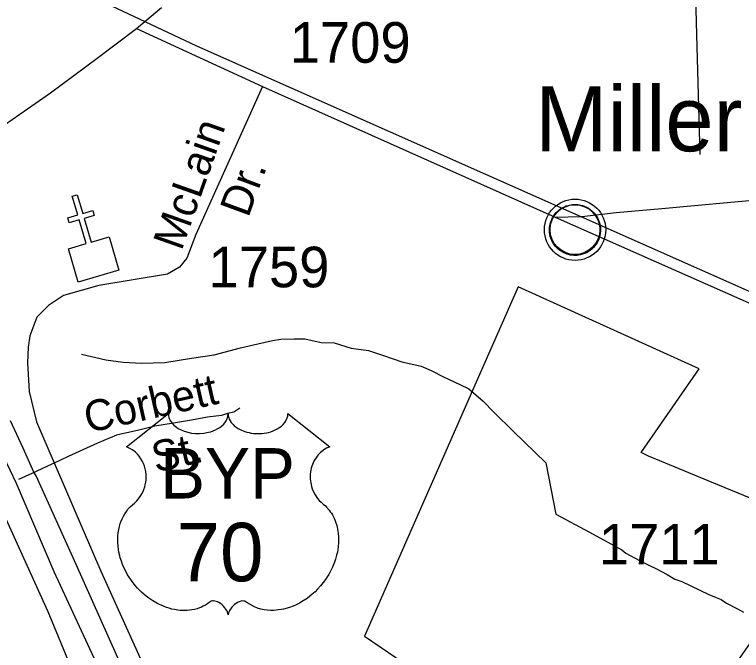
# Model space of a CAD drawing. Extents: x 2260773 to 2342389, y 552869 to 618546.
# Drawn here: x 2317310 to 2319547, y 592888 to 594846 of the extents above; entities that cross this region are included whole.
import ezdxf

# ---------------------------------------------------------------- set-up
doc = ezdxf.new("R2010")
doc.units = 0
for name, color, linetype in [('Exist Boundary Political City Limit New', 7, 'Continuous'), ('Exist Civil Demographics Community CELL', 7, 'Continuous'), ('Exist Civil Demographics Community Label', 7, 'Continuous'), ('Exist Cultural Church CELL', 7, 'Continuous'), ('Exist Hydrographic Misc Water Feature', 7, 'Continuous'), ('Exist Railroad Mainline', 7, 'Continuous'), ('Exist Road Non-System Type 51', 7, 'Continuous'), ('Exist Road Non-System Type 51 Label', 7, 'Continuous'), ('Exist Road Primary US Divided Attributed', 7, 'Continuous'), ('Exist Road Primary US Service Attributed', 7, 'Continuous'), ('Exist Road Primary US Shield CELL', 7, 'Continuous'), ('Exist Road Primary US Shield Number Label', 7, 'Continuous'), ('Exist Road Primary US UnDivided 4 Lane Attributed', 7, 'Continuous'), ('Exist Road Secondary Type 51 Attributed', 7, 'Continuous'), ('Exist Road Secondary Type 51 Label', 7, 'Continuous'), ('Exist Road Secondary Type 51 Number Label', 7, 'Continuous'), ('Map Preparation Boundary City Limit Buffer Line', 7, 'Continuous')]:
    doc.layers.add(name, color=color, linetype=linetype)

msp = doc.modelspace()

# ---------------------------------------------------------------- linework, layer by layer
at = {"layer": 'Exist Boundary Political City Limit New'}
msp.add_lwpolyline([(2319699.5, 593306.2), (2319462.5, 593403.4), (2319296, 593471.8), (2319261, 593486.1), (2319239, 593497.4), (2319416.8, 593755.6), (2318860, 594007.6), (2318730.8, 593714.1), (2318386.5, 592932.1), (2318483.8, 592866.8), (2318723.8, 592705.5), (2318740.8, 592693.9), (2318747.5, 592689.4), (2319027, 592500), (2319132.2, 592428), (2319184.8, 592392.1), (2319171.5, 592367.5), (2319166.5, 592358.4), (2319165, 592354.4), (2319162.2, 592346.7), (2319155.5, 592327.6), (2319153.8, 592322.2), (2319152.2, 592313.9)], dxfattribs=at)
at = {"layer": 'Exist Civil Demographics Community CELL'}
msp.add_lwpolyline([(2318957.4, 594195.7), (2318958.4, 594201.3), (2318960.2, 594207.9), (2318963.1, 594215.1), (2318966, 594220.8), (2318969.4, 594226.6), (2318973.1, 594231.7), (2318977.1, 594236.1), (2318981.7, 594240.7), (2318987.2, 594245.2), (2318992.6, 594248.9), (2318997.5, 594251.8), (2319002.6, 594254.2), (2319008, 594256.5), (2319013.7, 594258.3), (2319018, 594259.5), (2319022.8, 594260.2), (2319027, 594261), (2319033.3, 594261.2), (2319037.8, 594261.1), (2319043.4, 594260.8), (2319048.3, 594260.1), (2319053.2, 594259.1), (2319058.2, 594257.7), (2319063.4, 594255.8), (2319070.1, 594252.9), (2319076.3, 594249.4), (2319081.4, 594245.8), (2319086.6, 594241.8), (2319089.9, 594238.7), (2319094, 594234.3), (2319097.8, 594229.6), (2319100.9, 594225), (2319104.1, 594220), (2319106.5, 594214.8), (2319108.5, 594209.8), (2319110.1, 594204.8), (2319111.4, 594200.2), (2319112.5, 594194.2), (2319113.1, 594189.5), (2319113.4, 594183.5), (2319113.2, 594177.7), (2319112.6, 594172), (2319111.7, 594166.5), (2319110, 594160.4), (2319108.2, 594154.5), (2319105.9, 594149.4), (2319102.7, 594143.4), (2319099.4, 594138.1), (2319096, 594133.4), (2319091.7, 594128.7), (2319086.4, 594123.7), (2319081.4, 594119.6), (2319076.4, 594116.2), (2319072.1, 594113.7), (2319065.3, 594110.4), (2319058.1, 594107.7), (2319052.2, 594106.2), (2319045.6, 594104.9), (2319041.2, 594104.5), (2319036.7, 594104.2), (2319031.1, 594104.2), (2319026.8, 594104.6), (2319021.2, 594105.4), (2319015.2, 594106.7), (2319010.7, 594108), (2319005.5, 594109.8), (2319000.9, 594111.8), (2318997, 594114.1), (2318990.2, 594118.1), (2318984.6, 594122.4), (2318979.7, 594126.9), (2318975.2, 594131.8), (2318972, 594135.7), (2318969.1, 594139.9), (2318965, 594147), (2318963.3, 594150.5), (2318961.5, 594154.6), (2318958.9, 594162.8), (2318957.4, 594169.8), (2318956.7, 594175), (2318956.4, 594181.3), (2318956.3, 594186), (2318956.9, 594192.4)], close=True, dxfattribs=at)
for centre, radius in [((2319035, 594183.3), 94.3), ((2319034.8, 594183.6), 76.7)]:
    msp.add_circle(centre, radius, dxfattribs=at)
at = {"layer": 'Exist Cultural Church CELL'}
msp.add_lwpolyline([(2317475.4, 594124.4), (2317530, 594140.5), (2317508.7, 594213.6), (2317478, 594204.6), (2317473.5, 594220), (2317504.2, 594228.9), (2317487.4, 594286.7), (2317502.7, 594291.1), (2317519.6, 594233.4), (2317550.3, 594242.4), (2317554.8, 594227), (2317524.1, 594218.1), (2317545.4, 594145), (2317600.8, 594161), (2317630.6, 594058.8), (2317505.2, 594022.2)], close=True, dxfattribs=at)
at = {"layer": 'Exist Hydrographic Misc Water Feature'}
for points in [[(2319420.4, 594414.5), (2319411, 594746), (2319397.6, 595243.6), (2319386.4, 595709.2), (2319385.5, 595793.3), (2319373.8, 595807.2)], [(2317516.1, 593800.4), (2317590.3, 593783.2), (2317644.2, 593775.5), (2317700.2, 593772.3), (2317772, 593774.9), (2317854, 593787.7), (2317923.9, 593798.7), (2318005.5, 593819.7), (2318059.1, 593832.3), (2318103.3, 593842.6), (2318129.2, 593846.9), (2318170.8, 593847.5), (2318203.2, 593847.5), (2318253.2, 593836.3), (2318293.2, 593834.7), (2318345.5, 593819.1), (2318399, 593811.9), (2318445.4, 593796), (2318501.8, 593777), (2318561.8, 593763.5), (2318592, 593750), (2318630.3, 593730.1), (2318680.4, 593706.7), (2318708.2, 593693.2), (2318752.7, 593655.7), (2318785.3, 593622), (2318846, 593562.6), (2318944.7, 593465.8), (2318976.3, 593308.2), (2319079.6, 593252.8), (2319179.3, 593198.1), (2319191.8, 593188.1)], [(2319191.8, 593188.1), (2319233.6, 593164.8), (2319261.9, 593150.8), (2319285.9, 593139.1), (2319318.3, 593121.7), (2319342.3, 593107.9), (2319364, 593100.1), (2319446.8, 593060.9), (2319469, 593051.1), (2319485, 593045.4), (2319501, 593033.7), (2319535.4, 593016), (2319553.3, 593006.4)]]:
    msp.add_lwpolyline(points, dxfattribs=at)
at = {"layer": 'Exist Railroad Mainline'}
msp.add_line((2319052.5, 594224), (2320133.5, 593744), dxfattribs=at)
for points in [[(2316516.4, 595368.8), (2316557.9, 595354.7), (2316569.9, 595349.3), (2317194.7, 595067.6), (2317710.7, 594824.1)], [(2317710.7, 594824.1), (2317869.9, 594749), (2319052.5, 594224)]]:
    msp.add_lwpolyline(points, dxfattribs=at)
at = {"layer": 'Exist Road Non-System Type 51'}
for p, q in [((2317431.4, 593464.8), (2317424.1, 593461.5)), ((2317424.1, 593461.5), (2317362.6, 593433)), ((2317362.6, 593433), (2317321.8, 593414.1))]:
    msp.add_line(p, q, dxfattribs=at)
msp.add_lwpolyline([(2318003.4, 593634.5), (2317984.9, 593622.2), (2317964.9, 593617.5), (2317946.4, 593611.4), (2317903.4, 593606.8), (2317854.1, 593597.5), (2317798.8, 593588.3), (2317741.8, 593579.1), (2317692.6, 593566.8), (2317623.4, 593551.4), (2317564.9, 593526.7), (2317475.3, 593485.2), (2317431.4, 593464.8)], dxfattribs=at)
at = {"layer": 'Exist Road Primary US Divided Attributed'}
for points in [[(2318409.9, 591133.5), (2318220.5, 591549.2), (2318116.4, 591784.8), (2318091.6, 591843.1), (2318003.6, 592025.4), (2317970.1, 592106), (2317773, 592538.8), (2317499.1, 593152.7), (2317376.4, 593425.6), (2317369, 593436.7), (2317336.4, 593511.1), (2317297.8, 593595.3)], [(2317244.4, 593554), (2317265.1, 593510), (2317275.6, 593485.4), (2317314.4, 593403.3), (2317430.9, 593131.7), (2317716, 592515.3), (2317901.9, 592097.3), (2317947.8, 591995.6), (2318043.2, 591788.5), (2318070.5, 591727.7), (2318162.2, 591525.6), (2318372.4, 591066)]]:
    msp.add_lwpolyline(points, dxfattribs=at)
at = {"layer": 'Exist Road Primary US Service Attributed'}
msp.add_lwpolyline([(2316236.2, 593337.5), (2316558.7, 593496.8), (2316840.8, 593657.8), (2316918.8, 593687.9), (2316952.1, 593687.9), (2316985.3, 593677.8), (2317054.8, 593635.8), (2317111.3, 593580.8), (2317193.8, 593470.7), (2317228.5, 593407), (2317257.5, 593347.6), (2317412.3, 593007.9), (2317565.7, 592636.1), (2317936, 591832.5), (2318136.5, 591414.9), (2318181.6, 591293.3), (2318199.7, 591210.5), (2318199.7, 591136.7), (2318153.2, 590967.3), (2318163.6, 590922.3), (2318178, 590893.3), (2318207, 590860), (2318239.5, 590837.1)], dxfattribs=at)
at = {"layer": 'Exist Road Primary US Shield CELL'}
msp.add_lwpolyline([(2317783.3, 593617.3), (2317783.6, 593612), (2317784.9, 593605.7), (2317785.9, 593602.4), (2317788.9, 593596.2), (2317793.7, 593588.8), (2317800.5, 593581.6), (2317808.2, 593575.3), (2317813.4, 593571.9), (2317822.2, 593567.2), (2317832.1, 593563), (2317843.2, 593559.8), (2317854.5, 593557.6), (2317866.9, 593556.2), (2317879.1, 593556), (2317892.3, 593556.9), (2317906.9, 593559.8), (2317913.7, 593561.5), (2317921.2, 593564.1), (2317928.2, 593567), (2317935.8, 593571.1), (2317942, 593575), (2317946.8, 593578.5), (2317953.7, 593585.1), (2317959.1, 593591.8), (2317961.4, 593595.6), (2317963.3, 593599.3), (2317966, 593607), (2317966.8, 593610.4), (2317967.3, 593617.6), (2317967.8, 593611.6), (2317968.4, 593607.9), (2317969.4, 593604.2), (2317970.9, 593600.3), (2317973.6, 593594.9), (2317976.7, 593590.3), (2317982.4, 593583.5), (2317986, 593580.2), (2317989.2, 593577.5), (2317998, 593571.5), (2318008.2, 593566.4), (2318013.2, 593564.2), (2318018.4, 593562.3), (2318024.9, 593560.4), (2318031.7, 593558.8), (2318038.3, 593557.6), (2318045.2, 593556.6), (2318052.2, 593556.1), (2318057.9, 593556), (2318064.8, 593556), (2318071.3, 593556.4), (2318077.9, 593557.2), (2318085.2, 593558.4), (2318091, 593559.7), (2318098.8, 593561.7), (2318105.8, 593564.2), (2318111.9, 593566.9), (2318119.9, 593571.1), (2318126.4, 593575.1), (2318131.1, 593578.9), (2318136.7, 593584.1), (2318142, 593590.2), (2318145.1, 593594.7), (2318147.3, 593599.3), (2318149.4, 593604.2), (2318150.6, 593609.4), (2318151.2, 593613.9), (2318151.4, 593617.7), (2318280, 593515.2), (2318276.9, 593514.1), (2318269.9, 593510.7), (2318264.4, 593507.4), (2318255.5, 593501.2), (2318251.8, 593497.8), (2318248, 593494.2), (2318244.5, 593490.4), (2318241.4, 593486.8), (2318237.7, 593481.6), (2318234.3, 593476.5), (2318231.1, 593470.8), (2318228.7, 593465.8), (2318224.7, 593455.5), (2318222.8, 593449), (2318221.6, 593443.4), (2318220.1, 593431.9), (2318219.7, 593426.5), (2318219.7, 593421.1), (2318220, 593415.4), (2318220.5, 593409.9), (2318221.5, 593404.2), (2318222.4, 593399.2), (2318224, 593393), (2318226.3, 593385.9), (2318229.1, 593379), (2318235, 593367.8), (2318242.6, 593356.4), (2318247.9, 593350), (2318253.3, 593344.6), (2318261.2, 593337.9), (2318265.5, 593334.1), (2318270.4, 593329.1), (2318278.5, 593319.8), (2318281.7, 593315.4), (2318285, 593310.4), (2318288.1, 593305.4), (2318291.1, 593299.9), (2318293.6, 593295.1), (2318298.1, 593284.1), (2318301.4, 593273.4), (2318302.9, 593267.7), (2318305.3, 593255.1), (2318306.2, 593248.9), (2318307.2, 593236.6), (2318307.2, 593221.7), (2318306.1, 593207.6), (2318303.4, 593191.1), (2318301.2, 593181.2), (2318297.8, 593169.7), (2318294.6, 593159.8), (2318288.7, 593145.1), (2318283.5, 593134.5), (2318276.7, 593122), (2318272.1, 593114.5), (2318266.7, 593106.4), (2318260, 593097.2), (2318252, 593087.3), (2318242.6, 593076.9), (2318234.9, 593069.2), (2318224.9, 593060.2), (2318218.8, 593055.2), (2318210.1, 593048.7), (2318198.3, 593040.8), (2318186.6, 593034), (2318176.6, 593028.9), (2318167.8, 593025.1), (2318156.4, 593020.8), (2318137.4, 593015.5), (2318130.5, 593014.1), (2318122.3, 593012.9), (2318114.7, 593012.1), (2318107.2, 593011.7), (2318097.2, 593011.7), (2318087.2, 593012.4), (2318077.8, 593013.8), (2318068, 593015.8), (2318057.8, 593018.9), (2318048.5, 593022.5), (2318039.1, 593027.2), (2318023.1, 593037.2), (2318018.6, 593039.6), (2318016, 593040.3), (2318009.8, 593040.6), (2318004, 593039.4), (2317998.1, 593037), (2317994.6, 593035.1), (2317989.8, 593032), (2317986.2, 593029.1), (2317981.8, 593025), (2317978.7, 593021.5), (2317976.4, 593018.7), (2317971.9, 593011.7), (2317970.3, 593008.3), (2317968.7, 593004), (2317967.2, 592997.6), (2317965.2, 593005.7), (2317962.8, 593011), (2317960.1, 593015.5), (2317957.2, 593019.6), (2317952.7, 593024.7), (2317948.7, 593028.6), (2317943.9, 593032.6), (2317938.7, 593035.7), (2317934.6, 593037.8), (2317930.8, 593039.2), (2317926.1, 593040.4), (2317922.3, 593040.7), (2317919.2, 593040.6), (2317914.9, 593039.6), (2317909.1, 593035.4), (2317903.6, 593031.6), (2317897.6, 593027.9), (2317890.5, 593024.1), (2317885.2, 593021.7), (2317879, 593019.3), (2317871.7, 593016.8), (2317863.8, 593014.8), (2317855.7, 593013.2), (2317848.5, 593012), (2317840.9, 593011.4), (2317834, 593011.1), (2317826.7, 593011.2), (2317820, 593011.7), (2317812.2, 593012.4), (2317802.4, 593013.9), (2317794.4, 593015.7), (2317785.9, 593018), (2317777.2, 593020.7), (2317767.8, 593024.3), (2317756.1, 593029.4), (2317748, 593033.5), (2317735.2, 593040.9), (2317720.1, 593051.3), (2317708.8, 593060.5), (2317700.4, 593068), (2317688.2, 593080.5), (2317681, 593088.6), (2317669.8, 593103.2), (2317662.6, 593113.8), (2317657.9, 593121.5), (2317651, 593134), (2317647.3, 593141.8), (2317642.4, 593153.2), (2317638.6, 593163.6), (2317635.4, 593173.5), (2317633.7, 593179.8), (2317631.3, 593190.8), (2317629.8, 593198.7), (2317628.3, 593209.4), (2317627.5, 593220.7), (2317627.4, 593231.1), (2317627.7, 593239.8), (2317628.6, 593249.9), (2317630.4, 593260.6), (2317632.4, 593269.8), (2317634.3, 593276.4), (2317637, 593284.5), (2317640.6, 593293.3), (2317644.9, 593301.9), (2317648.9, 593308.9), (2317654, 593316.5), (2317659, 593323), (2317665.6, 593330.1), (2317672.4, 593336.7), (2317678.7, 593341.7), (2317686.1, 593349), (2317690, 593353.5), (2317694.7, 593359.6), (2317698.4, 593365.3), (2317701.4, 593370.4), (2317705.3, 593377.9), (2317707.6, 593383.5), (2317710.6, 593392.2), (2317712.1, 593398.3), (2317713.6, 593406.1), (2317714.6, 593413.5), (2317715, 593422.7), (2317714.7, 593430.3), (2317713.7, 593439.2), (2317712.1, 593447.7), (2317710.1, 593455.1), (2317706.9, 593463.6), (2317703.9, 593469.9), (2317699, 593478.3), (2317693.5, 593486.1), (2317687.9, 593492.5), (2317682.2, 593498.2), (2317676.7, 593502.5), (2317671.5, 593506.2), (2317665, 593510.1), (2317658.7, 593513.3), (2317654.7, 593514.8)], close=True, dxfattribs=at)
at = {"layer": 'Exist Road Primary US UnDivided 4 Lane Attributed'}
for p, q in [((2317710.7, 594824.1), (2317762.5, 594867.4)), ((2317685.1, 594802.8), (2317710.7, 594824.1))]:
    msp.add_line(p, q, dxfattribs=at)
msp.add_lwpolyline([(2317200.3, 594457.7), (2317278.4, 594506.5), (2317420.4, 594605), (2317564, 594711.6), (2317685.1, 594802.8)], dxfattribs=at)
at = {"layer": 'Exist Road Secondary Type 51 Attributed'}
for p, q in [((2317685.1, 594802.8), (2318073.2, 594624)), ((2318073.2, 594624), (2318974, 594222.5)), ((2318974, 594222.5), (2319052.5, 594224))]:
    msp.add_line(p, q, dxfattribs=at)
for points in [[(2319052.5, 594224), (2319055.5, 594224), (2319161.7, 594236.3), (2319301.7, 594248.6), (2319615.5, 594277.9), (2319721.6, 594290.2), (2319838.5, 594299.4), (2320029.3, 594316.4), (2320220, 594331.8), (2320817.7, 594376.5), (2321239.1, 594408), (2321442.2, 594417.3), (2321734.8, 594445.9), (2322082.9, 594484.2), (2322278.5, 594508.7), (2322409.7, 594532.3), (2322536.9, 594555.1), (2322613.5, 594576.4), (2322703.2, 594605.7), (2322779.8, 594638.3), (2322846.6, 594666.1), (2322977.1, 594739.5), (2323015.4, 594761.5), (2323039.8, 594779.4)], [(2318073.2, 594624), (2317868, 594168.6), (2317840.3, 594096.3), (2317817.2, 594068.6), (2317780.2, 594046.6), (2317569.6, 594011.6), (2317460.3, 593980.8), (2317414.2, 593950), (2317378.8, 593914.6), (2317357.3, 593856.7), (2317351.5, 593821.9), (2317350.1, 593774.1), (2317354.4, 593685.8), (2317377.6, 593591.6), (2317575.9, 593132.5), (2318025.1, 592139.2), (2318319.9, 591501.6), (2318367.6, 591445.2), (2318505.1, 591372.7), (2318534.6, 591345.6)], [(2318974, 594222.5), (2319950.8, 593789.9), (2320047, 593741.5), (2320071.6, 593719.9), (2320083.9, 593690.7), (2320080.8, 593656.8), (2320070, 593627.6), (2320027.4, 593564.1), (2319893.1, 593374.6), (2319836.5, 593294.8), (2319683.1, 593074.5), (2319573.7, 592911.8), (2319480.6, 592778.7), (2319366.8, 592610.1), (2319309.1, 592528.8), (2319248.7, 592442.7), (2319241.7, 592393.5), (2319241, 592373.8), (2319239, 592317.9), (2319247.2, 592261.7), (2319280.1, 592151.8)]]:
    msp.add_lwpolyline(points, dxfattribs=at)
at = {"layer": 'Map Preparation Boundary City Limit Buffer Line'}
msp.add_lwpolyline([(2319699.5, 593306.2), (2319462.5, 593403.4), (2319296, 593471.8), (2319261, 593486.1), (2319239, 593497.4), (2319416.8, 593755.6), (2318860, 594007.6), (2318730.8, 593714.1), (2318386.5, 592932.1), (2318483.8, 592866.8), (2318723.8, 592705.5), (2318740.8, 592693.9), (2318747.5, 592689.4), (2319027, 592500), (2319132.2, 592428), (2319184.8, 592392.1), (2319171.5, 592367.5), (2319166.5, 592358.4), (2319165, 592354.4), (2319162.2, 592346.7), (2319155.5, 592327.6), (2319153.8, 592322.2), (2319152.2, 592313.9)], dxfattribs=at)

# ---------------------------------------------------------------- texts
at = {"layer": 'Exist Civil Demographics Community Label'}
msp.add_text('Miller', height=200, dxfattribs=at).set_placement((2318911.9, 594424.9))
at = {"layer": 'Exist Road Non-System Type 51 Label'}
for s, rotation, p in [('Corbett', 12.7, (2317535.8, 593557.2)), ('St.', 13.3255, (2317744.8, 593435))]:
    msp.add_text(s, height=95, rotation=rotation, dxfattribs=at).set_placement(p)
at = {"layer": 'Exist Road Primary US Shield Number Label'}
for s, height, p in [('BYP', 155, (2317758, 593356)), ('70', 180, (2317808.5, 593101.1))]:
    msp.add_text(s, height=height, dxfattribs=at).set_placement(p)
at = {"layer": 'Exist Road Secondary Type 51 Label'}
for s, rotation, p in [('McLain', 70.5679, (2317823.9, 594115.9)), ('Dr.', 69.7751, (2318028.8, 594218))]:
    msp.add_text(s, height=95, rotation=rotation, dxfattribs=at).set_placement(p)
at = {"layer": 'Exist Road Secondary Type 51 Number Label'}
for s, p in [('1709', (2318157.1, 594697.4)), ('1759', (2317907.1, 594006.2)), ('1711', (2319108.4, 593152.9))]:
    msp.add_text(s, height=125, dxfattribs=at).set_placement(p)

doc.saveas('drawing.dxf')
